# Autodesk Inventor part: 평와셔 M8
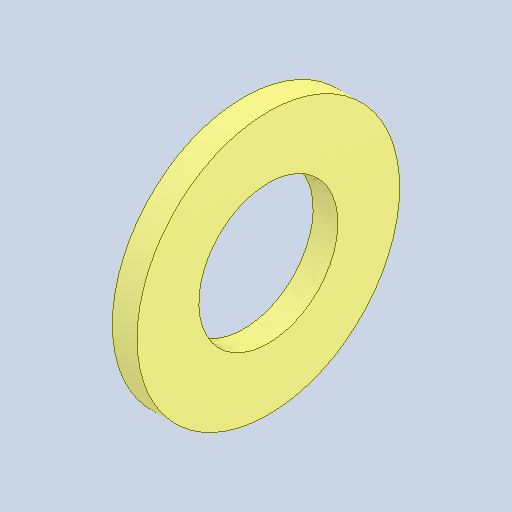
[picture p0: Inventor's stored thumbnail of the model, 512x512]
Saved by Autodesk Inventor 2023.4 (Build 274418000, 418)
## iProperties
Created: 2024-11
Part Number: 평와셔 M8
Material: 강철, 연강
Description: 평면 와셔
Document SubType Name: Modeling
Designer: EDU
Density: 7.85 g/cm^3
Appearance: 기본값
Author: jhkim
Sending System: Autodesk Inventor 2025
Preprocessor: ST-DEVELOPER v20
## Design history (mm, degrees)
feature "Solid1"
node "솔리드1"
